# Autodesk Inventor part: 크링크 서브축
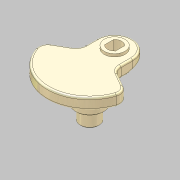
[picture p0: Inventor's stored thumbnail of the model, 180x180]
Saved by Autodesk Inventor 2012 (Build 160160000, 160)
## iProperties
Manager: KYOUNG IL JANG
Company: 한국ATC센터
Created: 2012-10
Part Number: 크링크 서브축
Document SubType Name: Modeling
Density: 1 g/cm^3
Checked By: KYOUNG IL JANG
Vendor: CBT Solutions
Designer: KYOUNG IL JANG
Material: 기본값
Author: KYOUNG IL JANG
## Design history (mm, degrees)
sketch "스케치1"
  geometry: L1 (-19, 109.368)-(-19, 91.368); L2 (-19, 91.368)-(-44.545, 76.619); L3 (19, 109.368)-(19, 91.368); L4 (19, 91.368)-(44.545, 76.619); C1 r 32.5 at (0, 83) reference; C2 r 10 at (0, 83); C3 r 17.5 at (0, 83); A1 r 45 centre (0, 83) between (-44.545, 76.619) and (44.545, 76.619); A2 r 32.5 centre (0, 83) between (-19, 109.368) and (19, 109.368); A3 r 19 centre (0, 109.368) between (19, 109.368) and (-19, 109.368); 1 further point
  constraints: 8 end point, 6 point on circle, 5 centre point, 4 coincident, 2 equal length, 1 horizontal alignment, 1 parallel, 1 tangent, 1 vertical, 1 vertical alignment
  dimensions: "d0" = 20 diameter of C2; "d1" = 35 diameter of C3; "d2" = 90 diameter of A1 (derived); "d3" = 65 diameter of A2 (derived); "d4" = 120 deg angle of L3 L4; "d5" = 19 radius of A3 (derived); "d6" = 18 distance of L1.start L1.end (derived)
  node "참조1"
extrude "돌출1" new body sketch "스케치1" distance "d7" = 12; taper "d8" = 0 deg
extrude "돌출2" join sketch "스케치1" distance "d9" = 5; taper "d10" = 0 deg
extrude "돌출3" join sketch "스케치1" distance "d11" = 41; taper "d12" = 0 deg
sketch "스케치2"
  geometry: C1 r 7.5 at (0, 109.368); C2 r 11 at (0, 109.368); A1 r 19 centre (0, 109.368) between (19, 109.368) and (-19, 109.368) reference; 1 further point
  constraints: 2 centre point, 2 coincident
  dimensions: "d13" = 15 diameter of C1; "d14" = 22 diameter of C2
extrude "돌출4" join sketch "스케치2" distance "d15" = 3; taper "d16" = 0 deg
extrude "돌출6" cut sketch "스케치2" stored distance "d19" = 10; taper "d20" = 0 deg
sketch "스케치3"
  geometry: L1 (-5.75, 4.815)-(-5.75, -4.815); L2 (5.75, 4.815)-(5.75, -4.815); A1 r 7.5 centre (0, 0) between (-5.75, 4.815) and (-5.75, -4.815) reference; 1 further point
  constraints: 4 end point, 4 point on circle, 2 parallel, 1 vertical
  dimensions: "d21" = 11.5 distance between parallel lines of L2 L1
extrude "돌출7" join sketch "스케치3" stored distance "d22" = 10; taper "d23" = 0 deg
sketch "스케치4"
  geometry: C1 r 10 at (0, 0) reference; C2 r 15 at (0, 0); 1 further point
  constraints: 1 centre point, 1 coincident
  dimensions: "d30" = 30 diameter of C2
extrude "돌출8" join sketch "스케치4" distance "d28" = 21; taper "d29" = 0 deg
chamfer "모따기1" distance "d31" = 1; stored, may be unused: second distance "d32" = 2, angle "d33" = 45 deg
sketch "스케치5"
  geometry: L1 (-19, 91.368)-(-19, 109.368) reference; L2 (19, 109.368)-(19, 91.368) reference; C1 r 9 at (0, 83); 3 further points
  constraints: 2 point on line, 1 centre point, 1 horizontal alignment
  dimensions: "d34" = 21 vertical distance of point (-19, 104) C1.centre (derived)
node "작업 평면1"
  node "작업축2"
sketch "스케치6"
  geometry: L1 (0, 50)-(38, 50); L2 (38, 50)-(38, 0); L3 (38, 0)-(0, 0); L4 (0, 0)-(0, 50); L5 (0, -12.202)-(0, 5.185) reference; L6 (38, 5.185)-(38, -12.202) reference; 2 further points
  constraints: 8 end point, 2 collinear, 1 point on line
  dimensions: "d37" = 50 distance from line of L1 L3.end
extrude "돌출9" cut sketch "스케치6" stored distance "d38" = 20.7; taper "d39" = 0 deg
fillet "모깎기1" dims "d26" = 10, "d27" = 2
node "솔리드1"
other parameters: "d35" = -15 deg (derived)
